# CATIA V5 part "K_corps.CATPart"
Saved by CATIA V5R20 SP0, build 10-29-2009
Part number: corps
Publications: "Corps principal", "Plan_pibot_bielle_1", "Point.4", "Point.5", "Plan.12", "Ecart_tige_corps"
Bounding box of the stored display mesh (mm): x -58 to 58, y -114.22 to 124, z 130 to 970
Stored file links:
  G:\Khaled_CFAO_2011\ST2M\ST2M_GR2\echouteau\Khaled\CAD_ThinkMotion\K_corps.CATPart
  F:\2A\Proj Think Motion\trainv3\Version3\sql_general.CATProduct
  G:\Khaled_CFAO_2011\ST2M\ST2M_GR2\echouteau\echouteau\bogie_beam.CATPart
  G:\Khaled_CFAO_2011\ST2M\ST2M_GR2\echouteau\Khaled\CAD_ThinkMotion\K_tige.CATPart
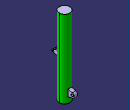
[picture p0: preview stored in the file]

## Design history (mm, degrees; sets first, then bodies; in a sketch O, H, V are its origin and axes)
Parameters
  Longueur_corps = 800 mm
  Ecart_tige_corps = 150 mm
Set1
  Plane1: linked copy from another document
  Line1: linked copy from another document
  Point1: linked copy from another document
Body1 (main body)
  Plane2: type Offset, RefPlane Plane1, Offset 800 {= Longueur_corps}
  Point2: type OnPlane, Support Plane2, H 0, V 0, Direction (1, 0, 0)
  Point3: type OnPlane, Support Plane1, H 0, V 0, Direction (1, 0, 0)
  Line2 "corps": type PtPt, FirstPoint Point2, SecondPoint Point3
  Point4: type OnCurve, Support Line2, Length 400
  Plane3: type OffsetPt, RefPlane Plane2, RefPoint Point4
  Point5: type OnPlane, Support Plane3, H 0, V -100, Direction (1, 0, 0)
  Line3: type PtPt, FirstPoint Point4, SecondPoint Point5
  Plane4: type Offset, RefPlane Plane1, Offset 80
  Point6: type OnPlane, Support Plane4, H 0, V 100, Direction (1, 0, 0)
  Point7: type OnPlane, Support Plane4, H 0, V 0, Direction (1, 0, 0)
  Line4: type PtPt, FirstPoint Point6, SecondPoint Point7, Support Plane4
  Plane5 "Plan_pibot_bielle_1": type Normal, Curve Line4, RefPoint Point7
  Plane6 "Plan_pivot_bielle_2": type Normal, Curve Line1, RefPoint Point1
  Plane7 "Plan_pivot_corps_corps_verin": type Normal, Curve Line3, RefPoint Point5
  Line5: type PtDir, RefPoint Point6, Direction yz-plane, Start 162, End 0
  Plane8: type OffsetPt, RefPlane yz-plane, RefPoint vertex of Line5
  Sketch1 on Plane2, origin (0, 0, 950), H (1, 0, 0), V (0, 1, 0)
    circle A1 centre (0, 0) radius 58
    point P1 (0, 0)
    reference projected point E1 (0, 0) from Point3
    coincidence: E1 P1
  Pad1: profile Sketch1, direction (0, 0, 1), up to Plane1, offset 20
  Sketch2 on yz-plane, origin (0, 0, 0), H (0, 1, 0), V (0, 0, 1)
    line L1 (-46, 577.8618) -> (-46, 523.7444)
    arc A1 centre (-100, 550) radius 14.223 from (-103.3818, 563.8151) to (-102.8351, 536.0625) ccw
    point P4 (-100, 550)
    line L2 (-46, 577.8618) -> (-103.3818, 563.8151)
    line L3 (-46, 523.7444) -> (-102.8351, 536.0625)
    reference projected point E1 (-100, 550) from Point5
    vertical: L1 V
    tangency: L2 A1
    coincidence: E1 P4
  Sketch3 on xy-plane, origin (0, 0, 0), H (1, 0, 0), V (0, 1, 0)
    point P1 (0, -53.5598)
    point P2 (22.4083, -47.9334)
    line L1 (22.4083, -47.9334) -> (22.4083, -123)
    point P3 (22.4083, -123)
    line L2 (22.4083, -123) -> (7, -123)
    point P4 (7, -123)
    line L3 (7, -123) -> (7, -60.0401)
    point P5 (7, -60.0401)
    line L4 (7, -60.0401) -> (0, -60.0401)
    point P6 (0, -60.0401)
    point P7 (-22.4083, -47.9334)
    point P8 (0, -60.0401)
    point P9 (-7, -60.0401)
    line L5 (-7, -60.0401) -> (0, -60.0401)
    point P10 (-7, -123)
    line L6 (-7, -123) -> (-7, -60.0401)
    point P11 (-22.4083, -123)
    line L7 (-22.4083, -47.9334) -> (-22.4083, -123)
    line L8 (-22.4083, -123) -> (-7, -123)
    line L9 (22.4083, -47.9334) -> (-22.4083, -47.9334)
    distance P4 P10 = 14
    coincidence: P1 V, P6 V, P6 P8
    vertical: L1 V, L3 V
    horizontal: L2 H, L4 H, L9 H
    symmetry: P2 P7 V, P6 P8 V, P5 P9 V, L4 L5 V, P4 P10 V, L3 L6 V, P3 P11 V, L1 L7 V, L2 L8 V
  SolidCombine1: FirstComponentProfile Sketch2, FirstComponentDirection Sketch2, SecondComponentProfile Sketch3, SecondComponentDirection Sketch3
  Sketch4 on face of SolidCombine1 from Sketch3.L1, origin (22.4083, -76.3013, 577.4425), H (0, 1, 0), V (0, 0, 1)
    point P1 (-23.6987, -27.4425)
    reference projected arc E1 centre (-23.6987, -27.4425) radius 14.223 from (-32.4846, -16.2577) to (-32.187, -38.8548) ccw from edge [face of SolidCombine1 from Sketch3.L1 | face of SolidCombine1 from Sketch2.A1]
    reference projected point E2 (-23.6987, -27.4425) from Point5
    concentricity: P1 E1
    coincidence: E2 P1
  Hole1: placed by Sketch4, at (22.4083, -100, 550) direction (-1, 0, 0), diameter 15, up to face of SolidCombine1 from Sketch3.L7
  Sketch5 on end face of Pad1, origin (0, 0, 130), H (1, 0, 0), V (0, -1, 0)
    point P1 (0, 0)
    construction circle A1 centre (0, 0) radius 54.5894
    point P2 (0, 0)
    reference projected point E1 (0, 0) from Point2
    coincidence: E1 P2
  Hole2: placed by Sketch5, at (0, 0, 130) direction (0, 0, 1), diameter 100, depth 1480
  Point8 to Point11: stored without definition
  Sketch6 on yz-plane, origin (0, 0, 0), H (0, 1, 0), V (0, 0, 1)
    arc A1 centre (100, 230) radius 24 from (103.72, 206.29) to (103.72, 253.71) ccw
    point P1 (100, 230)
    reference projected point E1 (100, 230) from Point8
    line L1 (103.72, 253.71) -> (0, 280)
    point P3 (0, 280)
    reference projected point E2 (0, 230) from Point9
    line L2 (0, 180) -> (103.72, 206.29)
    point P4 (0, 180)
    reference projected point E3 (0, 230) from Point10
    line L3 (0, 280) -> (0, 180)
    length L1 = 107
    distance P3 E2 = 50
    distance E3 P4 = 50
    length L2 = 107
    coincidence: P1 E1, P3 V, P4 V
    vertical: L3 V
  Sketch7 on zx-plane, origin (0, 0, 0), H (-1, 0, 0), V (0, 0, 1)
    line L1 (0, 267) -> (19, 267)
    point P1 (0, 267)
    point P2 (19, 267)
    line L2 (19, 267) -> (19, 193)
    point P3 (19, 193)
    line L3 (19, 193) -> (0, 193)
    point P4 (0, 193)
    reference intersected line E1 through (0, 0) direction (0, -1) from yz-plane
    point P7 (-19, 267)
    point P8 (0, 267)
    line L4 (0, 267) -> (-19, 267)
    point P9 (-19, 193)
    line L5 (-19, 267) -> (-19, 193)
    point P10 (0, 193)
    line L6 (-19, 193) -> (0, 193)
    reference projected point E2 (0, 230) from Point11
    distance P7 P2 = 38
    length L2 = 74
    distance E2 P1 = 37
    coincidence: P1 V, P4 V, P1 P8, P4 P10
    horizontal: L1 H, L3 H
    vertical: L2 V
    symmetry: P2 P7 E1, P1 P8 E1, L1 L4 E1, P3 P9 E1, L2 L5 E1, P4 P10 E1, L3 L6 E1
  SolidCombine2: FirstComponentProfile Sketch6, FirstComponentDirection Sketch6, SecondComponentProfile Sketch7, SecondComponentDirection Sketch7
  Line6: stored without definition
  Line7: type PtDir, RefPoint Point5, Direction Line6, Start 0, End 68
  Plane9: stored without definition
  Plane10: type OffsetPt, RefPlane Plane9, RefPoint vertex of Line7
  Sketch8 on face of SolidCombine2 from Sketch7.L5, origin (19, 107.795, 237.7896), H (0, 1, 0), V (0, 0, 1)
    point P1 (-7.795, -7.7896)
    reference projected arc E1 centre (-7.795, -7.7896) radius 24 from (-4.075, -31.4996) to (-4.075, 15.9203) ccw from Sketch6.A1
    concentricity: P1 E1
  Hole3: placed by Sketch8, at (19, 100, 230) direction (-1, 0, 0), diameter 24, up to face of SolidCombine2 from Sketch7.L2
  Plane11: type OffsetPt, RefPlane Plane10, RefPoint Point4
  Sketch9 on Plane2, origin (0, 0, 950), H (1, 0, 0), V (0, 1, 0)
    circle A1 centre (0, 0) radius 58
    point P1 (0, 0)
    reference projected point E1 (0, 0) from Point2
    coincidence: E1 P1
  Pad2: profile Sketch9, direction (0, 0, 1), length 20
